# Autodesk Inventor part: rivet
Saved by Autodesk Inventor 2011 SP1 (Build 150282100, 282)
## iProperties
Created: 2010-12
Part Number: rivet
Document SubType Name: Modeling
Designer: eric
Density: 1 g/cm^3
Author: eric
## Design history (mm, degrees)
feature "Base1"
node "Solide1"
node "Corps solides"
node "Corps surfaciques"
